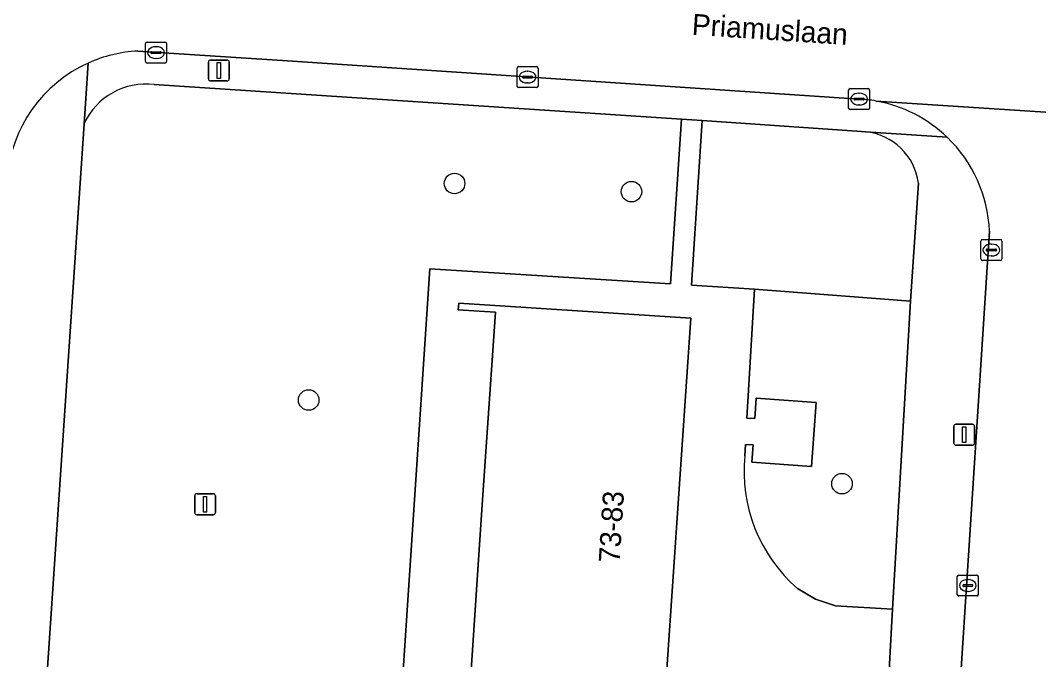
# Model space of a CAD drawing. Extents: x 161848 to 162726, y 385382 to 386521.
# Drawn here: x 162230.99 to 162279.5, y 385508.53 to 385539 of the extents above; entities that cross this region are included whole.
import ezdxf

# ---------------------------------------------------------------- set-up
doc = ezdxf.new("R2010")
doc.units = 0
for name, color, linetype in [('IMGEO_Boom', 7, 'Continuous'), ('IMGEO_Groenvoorziening', 7, 'Continuous'), ('IMGEO_Kolk', 7, 'Continuous'), ('IMGEO_Lichtmast', 7, 'Continuous'), ('IMGEO_Openbare_ruimte_label', 7, 'Continuous'), ('IMGEO_Pand', 7, 'Continuous'), ('IMGEO_Pand_nummerreeks', 7, 'Continuous'), ('IMGEO_Rijbaan_lokaal_open', 7, 'Continuous'), ('IMGEO_Verkeersbordpaal', 7, 'Continuous'), ('IMGEO_Voetpad_open', 7, 'Continuous')]:
    doc.layers.add(name, color=color, linetype=linetype)

msp = doc.modelspace()

# ---------------------------------------------------------------- linework, layer by layer
at = {"layer": 'IMGEO_Boom'}
for centre in [(162251.671, 385531.221), (162260.1, 385530.832), (162244.721, 385520.902), (162270.127, 385516.915)]:
    msp.add_circle(centre, 0.489, dxfattribs=at)
at = {"layer": 'IMGEO_Groenvoorziening'}
for points in [[(162227.271, 385391.248), (162241.486, 385391.457), (162250.499, 385527.157), (162261.965, 385526.444), (162262.479, 385534.283), (162237.367, 385535.933)], [(162234.018, 385534.066), (162225.467, 385407.267), (162224.546, 385394.477)], [(162271.241, 385533.689), (162271.061, 385533.701), (162263.466, 385534.217), (162262.952, 385526.381), (162265.961, 385526.178), (162273.391, 385525.618), (162273.776, 385531.24)], [(162273.391, 385525.618), (162265.961, 385526.178), (162265.602, 385520.039), (162265.98, 385520.017), (162266.048, 385520.989), (162268.891, 385520.791), (162268.677, 385517.734), (162265.834, 385517.933), (162265.893, 385518.768), (162265.529, 385518.79), (162265.497, 385518.248)], [(162268.005, 385511.915), (162268.871, 385511.409), (162269.823, 385511.092), (162272.54, 385510.932), (162273.391, 385525.618)]]:
    msp.add_lwpolyline(points, dxfattribs=at)
for centre, radius, start, end in [((162236.961, 385532.723), 3.235, 82.7992, 155.4784), ((162270.958, 385530.86), 2.843, 7.6826, 84.2945), ((162272.894, 385517.514), 7.433, 174.334, 228.8752)]:
    msp.add_arc(centre, radius, start, end, dxfattribs=at)
at = {"layer": 'IMGEO_Kolk'}
for p, q in [((162236.948, 385537.034), (162236.948, 385537.886)), ((162237.023, 385537.96), (162237.875, 385537.96)), ((162237.949, 385537.886), (162237.949, 385537.034)), ((162237.207, 385537.454), (162237.207, 385537.466)), ((162237.645, 385537.417), (162237.247, 385537.417)), ((162237.25, 385537.503), (162237.648, 385537.503)), ((162237.436, 385537.74), (162237.461, 385537.74)), ((162237.691, 385537.466), (162237.691, 385537.454)), ((162237.875, 385536.96), (162237.023, 385536.96)), ((162237.459, 385537.18), (162237.434, 385537.18)), ((162254.646, 385535.865), (162254.646, 385536.717)), ((162254.721, 385536.791), (162255.573, 385536.791)), ((162255.134, 385536.571), (162255.159, 385536.571)), ((162255.647, 385536.717), (162255.647, 385535.865)), ((162254.905, 385536.285), (162254.905, 385536.297)), ((162255.343, 385536.248), (162254.945, 385536.248)), ((162254.948, 385536.334), (162255.346, 385536.334)), ((162255.157, 385536.011), (162255.132, 385536.011)), ((162255.389, 385536.297), (162255.389, 385536.285)), ((162255.573, 385535.791), (162254.721, 385535.791)), ((162270.442, 385534.818), (162270.442, 385535.67)), ((162270.517, 385535.744), (162271.369, 385535.744)), ((162270.93, 385535.524), (162270.955, 385535.524)), ((162271.443, 385535.67), (162271.443, 385534.818)), ((162270.701, 385535.238), (162270.701, 385535.25)), ((162271.139, 385535.201), (162270.741, 385535.201)), ((162270.744, 385535.287), (162271.142, 385535.287)), ((162270.953, 385534.964), (162270.928, 385534.964)), ((162271.185, 385535.25), (162271.185, 385535.238)), ((162271.369, 385534.744), (162270.517, 385534.744)), ((162276.745, 385527.626), (162276.745, 385528.478)), ((162276.82, 385528.552), (162277.672, 385528.552)), ((162277.233, 385528.332), (162277.258, 385528.332)), ((162277.746, 385528.478), (162277.746, 385527.626)), ((162277.004, 385528.046), (162277.004, 385528.058)), ((162277.442, 385528.009), (162277.044, 385528.009)), ((162277.047, 385528.095), (162277.445, 385528.095)), ((162277.256, 385527.772), (162277.231, 385527.772)), ((162277.488, 385528.058), (162277.488, 385528.046)), ((162277.672, 385527.552), (162276.82, 385527.552)), ((162275.623, 385511.637), (162275.623, 385512.489)), ((162275.698, 385512.563), (162276.55, 385512.563)), ((162275.925, 385512.106), (162276.323, 385512.106)), ((162276.111, 385512.343), (162276.136, 385512.343)), ((162276.624, 385512.489), (162276.624, 385511.637)), ((162275.882, 385512.057), (162275.882, 385512.069)), ((162276.32, 385512.02), (162275.922, 385512.02)), ((162276.134, 385511.783), (162276.109, 385511.783)), ((162276.366, 385512.069), (162276.366, 385512.057)), ((162276.55, 385511.563), (162275.698, 385511.563))]:
    msp.add_line(p, q, dxfattribs=at)
for points in [[(162236.948, 385537.034), (162236.948, 385537.886)], [(162237.023, 385537.96), (162237.875, 385537.96)], [(162237.949, 385537.886), (162237.949, 385537.034)], [(162237.875, 385536.96), (162237.023, 385536.96)], [(162254.646, 385535.865), (162254.646, 385536.717)], [(162254.721, 385536.791), (162255.573, 385536.791)], [(162255.647, 385536.717), (162255.647, 385535.865)], [(162255.573, 385535.791), (162254.721, 385535.791)], [(162270.442, 385534.818), (162270.442, 385535.67)], [(162270.517, 385535.744), (162271.369, 385535.744)], [(162271.443, 385535.67), (162271.443, 385534.818)], [(162271.369, 385534.744), (162270.517, 385534.744)], [(162276.745, 385527.626), (162276.745, 385528.478)], [(162276.82, 385528.552), (162277.672, 385528.552)], [(162277.746, 385528.478), (162277.746, 385527.626)], [(162277.672, 385527.552), (162276.82, 385527.552)], [(162275.623, 385511.637), (162275.623, 385512.489)], [(162275.698, 385512.563), (162276.55, 385512.563)], [(162276.624, 385512.489), (162276.624, 385511.637)], [(162276.55, 385511.563), (162275.698, 385511.563)]]:
    msp.add_lwpolyline(points, dxfattribs=at)
for centre, radius, start, end in [((162237.025, 385537.884), 0.0765, 91.552, 178.448), ((162237.025, 385537.884), 0.0765, 91.552, 178.448), ((162237.873, 385537.884), 0.0765, 1.552, 88.448), ((162237.873, 385537.884), 0.0765, 1.552, 88.448), ((162237.247, 385537.463), 0.0403, 85.8775, 175.7526), ((162237.244, 385537.453), 0.0366, 178.938, 274.7102), ((162237.648, 385537.46), 0.043, 264.8664, 352.4533), ((162237.652, 385537.465), 0.0386, 1.7309, 96.639), ((162237.025, 385537.036), 0.0765, 181.552, 268.448), ((162237.025, 385537.036), 0.0765, 181.552, 268.448), ((162237.873, 385537.036), 0.0765, 271.552, 358.448), ((162237.873, 385537.036), 0.0765, 271.552, 358.448), ((162254.723, 385536.715), 0.0765, 91.552, 178.448), ((162254.723, 385536.715), 0.0765, 91.552, 178.448), ((162255.571, 385536.715), 0.0765, 1.552, 88.448), ((162255.571, 385536.715), 0.0765, 1.552, 88.448), ((162254.945, 385536.294), 0.0403, 85.8775, 175.7526), ((162254.942, 385536.284), 0.0366, 178.938, 274.7102), ((162255.346, 385536.291), 0.043, 264.8664, 352.4533), ((162255.35, 385536.296), 0.0386, 1.7309, 96.639), ((162254.723, 385535.867), 0.0765, 181.552, 268.448), ((162254.723, 385535.867), 0.0765, 181.552, 268.448), ((162255.571, 385535.867), 0.0765, 271.552, 358.448), ((162255.571, 385535.867), 0.0765, 271.552, 358.448), ((162270.519, 385535.668), 0.0765, 91.552, 178.448), ((162270.519, 385535.668), 0.0765, 91.552, 178.448), ((162271.367, 385535.668), 0.0765, 1.552, 88.448), ((162271.367, 385535.668), 0.0765, 1.552, 88.448), ((162270.741, 385535.247), 0.0403, 85.8775, 175.7526), ((162270.738, 385535.237), 0.0366, 178.938, 274.7102), ((162271.142, 385535.244), 0.043, 264.8664, 352.4533), ((162271.146, 385535.249), 0.0386, 1.7309, 96.639), ((162270.519, 385534.82), 0.0765, 181.552, 268.448), ((162270.519, 385534.82), 0.0765, 181.552, 268.448), ((162271.367, 385534.82), 0.0765, 271.552, 358.448), ((162271.367, 385534.82), 0.0765, 271.552, 358.448), ((162276.822, 385528.476), 0.0765, 91.552, 178.448), ((162276.822, 385528.476), 0.0765, 91.552, 178.448), ((162277.67, 385528.476), 0.0765, 1.552, 88.448), ((162277.67, 385528.476), 0.0765, 1.552, 88.448), ((162277.044, 385528.055), 0.0403, 85.8775, 175.7526), ((162277.041, 385528.045), 0.0366, 178.938, 274.7102), ((162277.445, 385528.052), 0.043, 264.8664, 352.4533), ((162277.449, 385528.057), 0.0386, 1.7309, 96.639), ((162276.822, 385527.628), 0.0765, 181.552, 268.448), ((162276.822, 385527.628), 0.0765, 181.552, 268.448), ((162277.67, 385527.628), 0.0765, 271.552, 358.448), ((162277.67, 385527.628), 0.0765, 271.552, 358.448), ((162275.7, 385512.487), 0.0765, 91.552, 178.448), ((162275.7, 385512.487), 0.0765, 91.552, 178.448), ((162275.922, 385512.066), 0.0403, 85.8775, 175.7526), ((162276.327, 385512.068), 0.0386, 1.7309, 96.639), ((162276.548, 385512.487), 0.0765, 1.552, 88.448), ((162276.548, 385512.487), 0.0765, 1.552, 88.448), ((162275.7, 385511.639), 0.0765, 181.552, 268.448), ((162275.7, 385511.639), 0.0765, 181.552, 268.448), ((162275.919, 385512.056), 0.0366, 178.938, 274.7102), ((162276.323, 385512.063), 0.043, 264.8664, 352.4533), ((162276.548, 385511.639), 0.0765, 271.552, 358.448), ((162276.548, 385511.639), 0.0765, 271.552, 358.448)]:
    msp.add_arc(centre, radius, start, end, dxfattribs=at)
for centre, major_axis, ratio, start_param, end_param in [((162237.435, 385537.46), (-0.387, 0.002), 0.722429, 4.712389, 7.853982), ((162237.46, 385537.46), (-0.39, 0.002), 0.717154, 1.570796, 4.712389), ((162255.133, 385536.291), (-0.387, 0.002), 0.722429, 4.712389, 7.853982), ((162255.158, 385536.291), (-0.39, 0.002), 0.717154, 1.570796, 4.712389), ((162270.929, 385535.244), (-0.387, 0.002), 0.722429, 4.712389, 7.853982), ((162270.954, 385535.244), (-0.39, 0.002), 0.717154, 1.570796, 4.712389), ((162277.232, 385528.052), (-0.387, 0.002), 0.722429, 4.712389, 7.853982), ((162277.257, 385528.052), (-0.39, 0.002), 0.717154, 1.570796, 4.712389), ((162276.11, 385512.063), (-0.387, 0.002), 0.722429, 4.712389, 7.853982), ((162276.135, 385512.063), (-0.39, 0.002), 0.717154, 1.570796, 4.712389)]:
    msp.add_ellipse(centre, major_axis=major_axis, ratio=ratio, start_param=start_param, end_param=end_param, dxfattribs=at)
at = {"layer": 'IMGEO_Lichtmast'}
for p, q in [((162239.947, 385536.206), (162239.947, 385537.006)), ((162239.947, 385537.006), (162239.947, 385536.206)), ((162240.047, 385537.106), (162240.837, 385537.106)), ((162240.837, 385537.106), (162240.047, 385537.106)), ((162240.937, 385537.006), (162240.937, 385536.206)), ((162240.937, 385536.206), (162240.937, 385537.006)), ((162240.837, 385536.106), (162240.047, 385536.106)), ((162240.047, 385536.106), (162240.837, 385536.106)), ((162275.455, 385518.846), (162275.455, 385519.646)), ((162275.455, 385519.646), (162275.455, 385518.846)), ((162275.555, 385519.746), (162276.345, 385519.746)), ((162276.345, 385519.746), (162275.555, 385519.746)), ((162276.445, 385519.646), (162276.445, 385518.846)), ((162276.445, 385518.846), (162276.445, 385519.646)), ((162276.345, 385518.746), (162275.555, 385518.746)), ((162275.555, 385518.746), (162276.345, 385518.746))]:
    msp.add_line(p, q, dxfattribs=at)
for points in [[(162240.367, 385536.981), (162240.517, 385536.981), (162240.517, 385536.231), (162240.367, 385536.231), (162240.367, 385536.981)], [(162275.875, 385519.621), (162276.025, 385519.621), (162276.025, 385518.871), (162275.875, 385518.871), (162275.875, 385519.621)]]:
    msp.add_lwpolyline(points, dxfattribs=at)
for centre, start, end in [((162240.047, 385537.006), 90, 180), ((162240.047, 385537.006), 90, 180), ((162240.837, 385537.006), 0, 90), ((162240.837, 385537.006), 360, 90), ((162240.047, 385536.206), 180, 270), ((162240.047, 385536.206), 180, 270), ((162240.837, 385536.206), 270, 0), ((162240.837, 385536.206), 270, 0), ((162275.555, 385519.646), 90, 180), ((162275.555, 385519.646), 90, 180), ((162276.345, 385519.646), 0, 90), ((162276.345, 385519.646), 360, 90), ((162275.555, 385518.846), 180, 270), ((162275.555, 385518.846), 180, 270), ((162276.345, 385518.846), 270, 0), ((162276.345, 385518.846), 270, 0)]:
    msp.add_arc(centre, 0.1, start, end, dxfattribs=at)
at = {"layer": 'IMGEO_Pand'}
msp.add_lwpolyline([(162261.668, 385506.443), (162262.286, 385515.504), (162262.92, 385524.799), (162251.867, 385525.514), (162251.847, 385525.203), (162252.845, 385525.138), (162253.62, 385525.088), (162253.01, 385516.145), (162252.392, 385507.083)], close=True, dxfattribs=at)
at = {"layer": 'IMGEO_Rijbaan_lokaal_open'}
for points in [[(162236.575, 385537.534), (162243.717, 385537.059), (162270.947, 385535.245)], [(162271.756, 385535.151), (162289.851, 385533.969)], [(162289.851, 385533.969), (162271.756, 385535.151)], [(162277.154, 385528.957), (162275.279, 385500), (162273.331, 385471.78), (162273.234, 385470.171)]]:
    msp.add_lwpolyline(points, dxfattribs=at)
for centre, radius, start, end in [((162236.911, 385530.994), 6.548, 92.9411, 114.3309), ((162236.918, 385530.965), 6.578, 114.2777, 175.4804), ((162270.621, 385528.911), 6.343, 79.6912, 87.0535), ((162270.593, 385528.686), 6.569, 46.1613, 79.8055), ((162270.595, 385528.69), 6.564, 2.328, 46.1456)]:
    msp.add_arc(centre, radius, start, end, dxfattribs=at)
at = {"layer": 'IMGEO_Verkeersbordpaal'}
for p, q in [((162239.29, 385515.535), (162239.29, 385516.335)), ((162239.29, 385516.335), (162239.29, 385515.535)), ((162239.39, 385516.435), (162240.18, 385516.435)), ((162240.18, 385516.435), (162239.39, 385516.435)), ((162240.28, 385516.335), (162240.28, 385515.535)), ((162240.28, 385515.535), (162240.28, 385516.335)), ((162240.18, 385515.435), (162239.39, 385515.435)), ((162239.39, 385515.435), (162240.18, 385515.435))]:
    msp.add_line(p, q, dxfattribs=at)
msp.add_lwpolyline([(162239.71, 385516.31), (162239.86, 385516.31), (162239.86, 385515.56), (162239.71, 385515.56), (162239.71, 385516.31)], dxfattribs=at)
for centre, start, end in [((162239.39, 385516.335), 90, 180), ((162239.39, 385516.335), 90, 180), ((162240.18, 385516.335), 0, 90), ((162240.18, 385516.335), 360, 90), ((162239.39, 385515.535), 180, 270), ((162239.39, 385515.535), 180, 270), ((162240.18, 385515.535), 270, 0), ((162240.18, 385515.535), 270, 0)]:
    msp.add_arc(centre, 0.1, start, end, dxfattribs=at)
at = {"layer": 'IMGEO_Voetpad_open'}
for points in [[(162243.717, 385537.059), (162236.575, 385537.534)], [(162234.018, 385534.066), (162234.213, 385536.961)], [(162234.213, 385536.961), (162234.018, 385534.066)], [(162270.947, 385535.245), (162243.717, 385537.059)], [(162237.367, 385535.933), (162262.479, 385534.283), (162263.466, 385534.217), (162271.061, 385533.701), (162271.241, 385533.689), (162275.143, 385533.424)], [(162224.546, 385394.477), (162225.467, 385407.267), (162234.018, 385534.066)], [(162265.497, 385518.248), (162265.529, 385518.79), (162265.893, 385518.768), (162265.834, 385517.933), (162268.677, 385517.734), (162268.891, 385520.791), (162266.048, 385520.989), (162265.98, 385520.017), (162265.602, 385520.039), (162265.961, 385526.178), (162262.952, 385526.381), (162263.466, 385534.217), (162262.479, 385534.283), (162261.965, 385526.444), (162250.499, 385527.157), (162241.486, 385391.457), (162243.197, 385391.482), (162243.301, 385395.075), (162255.477, 385394.425), (162255.343, 385391.66), (162257.257, 385391.689), (162257.254, 385391.956)], [(162275.143, 385533.424), (162271.241, 385533.689)], [(162273.776, 385531.24), (162273.391, 385525.618), (162272.54, 385510.932), (162272.356, 385507.75), (162271.812, 385500), (162271.222, 385492.992), (162270.894, 385489.82), (162269.853, 385474.089), (162269.753, 385471.068), (162268.704, 385456.607), (162268.527, 385453.246), (162267.563, 385437.996), (162267.337, 385434.743), (162266.246, 385419.052), (162266.047, 385415.86), (162265.301, 385404.029), (162265.103, 385400.915), (162264.862, 385397.867), (162264.665, 385394.839)], [(162273.234, 385470.171), (162273.331, 385471.78), (162275.279, 385500), (162277.154, 385528.957)], [(162248.624, 385451.841), (162249.879, 385470.239), (162251.134, 385488.636), (162251.909, 385500), (162252.392, 385507.083), (162253.01, 385516.145), (162253.62, 385525.088), (162252.845, 385525.138), (162251.847, 385525.203), (162251.867, 385525.514), (162262.92, 385524.799), (162262.286, 385515.504), (162261.668, 385506.443), (162261.229, 385500), (162260.411, 385488.004), (162259.156, 385469.606), (162257.902, 385451.209)], [(162268.448, 385507.575), (162270.396, 385507.788), (162272.356, 385507.75), (162272.54, 385510.932), (162269.823, 385511.092), (162268.871, 385511.409), (162268.005, 385511.915)]]:
    msp.add_lwpolyline(points, dxfattribs=at)
for centre, radius, start, end in [((162236.911, 385530.994), 6.548, 92.9411, 114.3309), ((162236.918, 385530.965), 6.578, 114.2777, 175.4804), ((162236.961, 385532.723), 3.235, 82.7992, 155.4784), ((162270.621, 385528.911), 6.343, 79.6912, 87.0535), ((162270.593, 385528.686), 6.569, 46.1613, 79.8055), ((162270.958, 385530.86), 2.843, 7.6826, 84.2945), ((162270.595, 385528.69), 6.564, 2.328, 46.1456), ((162272.894, 385517.514), 7.433, 174.334, 228.8752)]:
    msp.add_arc(centre, radius, start, end, dxfattribs=at)

# ---------------------------------------------------------------- texts
at = {"layer": 'IMGEO_Openbare_ruimte_label'}
msp.add_text('Priamuslaan', height=1, rotation=356.2164, dxfattribs=at).set_placement((162262.954, 385538.314))
at = {"layer": 'IMGEO_Pand_nummerreeks'}
msp.add_text('73-83', height=1, rotation=86.4308, dxfattribs=at).set_placement((162259.535, 385513.123))

doc.saveas('drawing.dxf')
